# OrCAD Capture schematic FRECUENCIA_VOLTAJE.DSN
size A
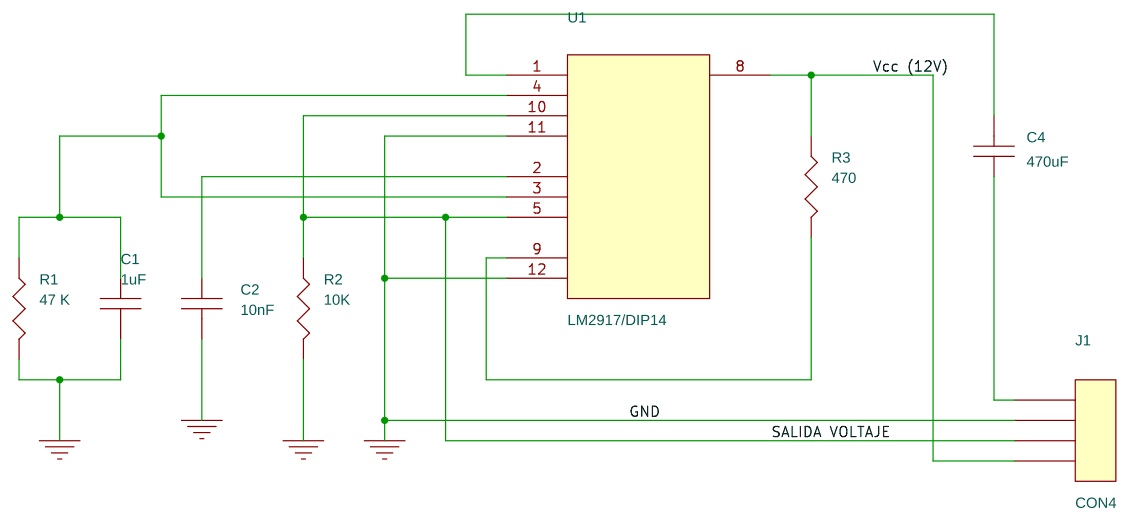
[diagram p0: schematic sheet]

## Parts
C1  1uF
C2  10nF
C4  470uF
J1  CON4
R1  47 K
R2  10K
R3  470
U1  LM2917/DIP14

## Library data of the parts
C1 C2 C4 = C
J1 = CON4
R1-R3 = R
U1 = LM2917_DIP14

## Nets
Vcc (12V): J1.4 R3.1 U1.8
0: C1.2 C2.2 J1.2 R1.2 R2.2 U1.11 U1.12
SALIDA VOLTAJE: J1.3 R2.1 U1.5 U1.10
N00450: C1.1 R1.1 U1.3 U1.4
N00735: C2.1 U1.2
N01256: R3.2 U1.9
N01331: C4.2 U1.1
N02504: C4.1 J1.1
